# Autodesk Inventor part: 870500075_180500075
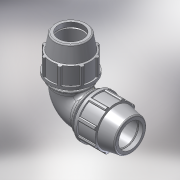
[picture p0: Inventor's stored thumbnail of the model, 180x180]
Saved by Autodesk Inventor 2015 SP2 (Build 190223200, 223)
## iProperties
Created: 2017-02
Part Number: 870500075_180500075
Material: PVC-Piping
Description: PLASSON 90° ELBOW 75-75
Document SubType Name: Modeling
Designer: KIM
Mass: 92.6774 g
Surface Area: 199.44 cm^2
Volume: 66.1981 cm^3
Density: 1.4 g/cm^3
Appearance: Smooth - White
Author: KIM
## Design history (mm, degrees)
derived "87050.ipt"
feature "Solid1::87050.ipt"
tag "TaggingFeature1"
body "Solid1"
other parameters: "d2" = 75, "d4" = 15.33333, "d5" = 46, "d7" = 132, "d9" = 26.28571, "d11" = 6.13333, "d13" = 120 deg, "d14" = 97.5, "d15" = 10 deg, "d16" = 114.84, "d18" = 3.75, "d19" = 35 deg, "d20" = 17.5 deg, "d21" = 122.76, "d23" = 0, "d25" = 360 deg, "d27" = 2.64, "d33" = 1.5, "d42" = 62.56, "d43" = 3.96, "d46" = 2.25, "d51" = 184, "d59" = 90 deg, "d63" = 137, "d64" = 67.5, "d67" = 99, "d68" = 11.04, "d70" = 90 deg, "d71" = 11.25, "d72" = 8.8, "d73" = 0, "d75" = 90 deg, "d77" = 112.5432, "d78" = 3.68, "d_" = 75, "E_" = 132, "A_" = 184, "l_" = 137
